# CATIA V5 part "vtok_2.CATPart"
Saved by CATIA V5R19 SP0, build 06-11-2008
Part number: LEGO_v3.1.2
Source: Unknown
Bounding box of the stored display mesh (mm): x -5.907 to 5.893, y 0 to 16.735, z -2.795 to 0
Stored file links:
  C:\Users\jsmid\Desktop\DP_Smidak_Forma LEGO\vtok_2.CATPart
  C:\Users\jsmid\Desktop\Forma_kostka\Babyplast_univ_ram_plus_LEGO_2.CATProduct
  C:\Users\jsmid\Desktop\Forma_kostka\DOC219.CATPart
  Product8.CATProduct
  C:\Users\jsmid\Desktop\Forma_kostka\tvarnik_1.1.CATPart
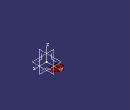
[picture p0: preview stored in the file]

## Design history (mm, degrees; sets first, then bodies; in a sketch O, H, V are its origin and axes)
Parameters
  DraftAngle = 0 deg
  Tesselation1 = 0.01 mm
  Tesselation2 = -1 mm
  `Compute Mode` = 0
  ValExplode = 10 mm
  Stroke = 0 mm
  `Stroke Angle` = 0 deg
AxisSystem1 "Main Pulling Direction.1": origin (0, 0, 0), X (1, 0, 0), Y (0, 1, 0), Z (0, 0, 1)
Set1
  Sketch1 on face of Solid1, origin (0, 0, 0), H (1, 0, 0), V (0, 1, 0)
    line L1 (-1.9073, 13.9547) -> (-1.9073, 12.8178)
    point P2 (-1.9073, 12.8178)
    line L2 (-1.9073, 12.8178) -> (1.8926, 12.8178)
    point P3 (1.8926, 12.8178)
    line L3 (1.8926, 12.8178) -> (1.7576, 12.2309)
    point P4 (1.7576, 12.2309)
    line L4 (1.7576, 12.2309) -> (-1.7723, 12.2309)
    point P5 (-1.7723, 12.2309)
    line L5 (-1.7723, 12.2309) -> (-1.0074, 8.9066)
    point P6 (-1.0074, 8.9066)
    line L6 (-1.0074, 8.9066) -> (0.9927, 8.9066)
    point P7 (0.9927, 8.9066)
    reference projected line E1 (-1.9073, 14.4251) -> (-1.9073, 12.7349) from edge [face of Solid1 | face of Solid1]
    reference projected line E2 (1.8927, 12.7349) -> (1.8926, 14.4251) from edge [face of Solid1 | face of Solid1]
    reference projected line E3 (1.8927, 12.7349) -> (1.4415, 11.0513) from edge [face of Solid1 | face of Solid1]
    reference projected line E4 (-1.4562, 11.0513) -> (-1.9073, 12.7349) from edge [face of Solid1 | face of Solid1]
    reference projected line E5 (-1.0073, 10.1426) -> (-1.0074, 7.9395) from edge [face of Solid1 | face of Solid1]
    reference projected line E6 (0.9927, 10.1426) -> (0.9927, 7.9395) from edge [face of Solid1 | face of Solid1]
    line L7 (-1.4592, 11.195) -> (1.4675, 11.195)
    point P10 (0.9927, 10.1426)
    line L8 (0.9927, 10.1426) -> (0.9927, 6.7335)
    reference projected point E7 (0.9927, 10.1426) from vertex [face of Solid1 | face of Solid1 | face of Solid1]
    length L6 = 2
    length L2 = 3.8
    length L7 = 2.9268
    length L8 = 3.4091
    vertical: L1 V, L8 V
    horizontal: L2 H, L4 H, L6 H, L7 H
    coincidence: L5 P2, P2 E1, P3 E2, P4 E3, P5 E4, P6 E5, P7 E6, E7 P10
  Line1: type PtDir, Direction (1, 0, 0), Start 0, End 4, RefPoint vertex [face of DatumSurface17]
  Line2: type PtDir, Direction (1, 0, 0), Start 0, End 4, RefPoint vertex [face of DatumSurface17 | face of DatumSurface17]
  Line3: type PtDir, Direction (0, 1, 0), Start 0, End 4, RefPoint vertex of Line2
  Line4: type PtDir, Direction (0, 1, 0), Start 0, End 4, RefPoint vertex [face of DatumSurface17 | face of DatumSurface17]
  Line5: type PtDir, Direction (1, 0, 0), Start 0, End 4, RefPoint vertex of Line4
  Line6: type PtDir, Direction (1, 0, 0), Start 0, End 4, RefPoint vertex [face of DatumSurface17]
  Line7: type PtDir, Direction (1, 0, 0), Start 0, End 4, RefPoint vertex [face of DatumSurface1]
  Line8: type PtDir, Direction (0, 1, 0), Start 0, End 4, RefPoint vertex of Line7
  Line9: type PtDir, Direction (0, 1, 0), Start 0, End 4, RefPoint vertex [face of DatumSurface1 | face of DatumSurface1]
  Line10: type PtDir, Direction (1, 0, 0), Start 0, End 4, RefPoint vertex of Line9
  Line11: type PtPt, SecondPoint vertex of Line6, FirstPoint vertex of Line5
  Line12: type PtPt, SecondPoint vertex of Line7, FirstPoint vertex of Line6
  Line13: type PtPt, SecondPoint vertex of Line8, FirstPoint vertex of Line7
  Line14: type PtPt, SecondPoint vertex of Line9, FirstPoint vertex of Line8
  Line15: type PtPt, SecondPoint vertex of Line10, FirstPoint vertex of Line9
  Line16: type PtPt, SecondPoint vertex of Line1, FirstPoint vertex of Line10
  Line17: type PtPt, SecondPoint vertex of Line2, FirstPoint vertex of Line1
  Line18: type PtPt, SecondPoint vertex of Line3, FirstPoint vertex of Line2
  Line19: type PtPt, SecondPoint vertex of Line4, FirstPoint vertex of Line3
  Line20: type PtPt, SecondPoint vertex of Line5, FirstPoint vertex of Line4
  Line21: type PtPt, SecondPoint vertex [face of DatumSurface1], FirstPoint vertex [face of DatumSurface1]
  Line22: type PtDir, Direction (0, 1, 0), Start 0, End 0.5, RefPoint vertex [face of Fill4]
  Line23: type PtDir, Direction (0, 1, 0), Start 0, End 0.5, RefPoint vertex [face of Fill3]
  Line24: type PtPt, SecondPoint vertex of Line23, FirstPoint vertex of Line22
  Sketch2 on DatumSurface7, origin (0, 0, 0), H (1, 0, 0), V (0, 1, 0)
    line L1 (-4.2727, 6.7395) -> (5.6211, 6.7395)
    reference projected line E1 (0.0039, 6.7405) -> (-0.0186, 6.7405) from edge of DatumSurface7
    distance E1 L1 = 0.001
    horizontal: L1 H
Set2 "Core.1"
  DatumSurface1 "TrfSurface.12"
  Fill1: Boundary (edge of DatumSurface1; Line9; Line14; Line8)
  Fill2: Boundary (Line8; Line13; Line7)
  Fill3: Boundary (edge of DatumSurface17; edge of DatumSurface17; edge of DatumSurface1; Line6; Line12; Line7)
  Fill4: Boundary (edge of DatumSurface1; edge of DatumSurface17; edge of DatumSurface1; Line10; Line16; Line1)
  Fill5: Boundary (Line10; Line9; Line15)
  DatumSurface2 "TrfSurface.23"
  DatumSurface3 "TrfSurface.24"
  DatumSurface4 "TrfSurface.25"
  DatumSurface5 "TrfSurface.26"
  DatumSurface6 "TrfSurface.27"
  DatumSurface7 "TrfSurface.28"
  DatumSurface8 "TrfSurface.29"
  Split1: ToCut DatumSurface6, Cutting Sketch2
  Split2: ToCut DatumSurface7, Cutting Sketch2
  Split3: ToCut DatumSurface8, Cutting Sketch2
  Join1: Elements (DatumSurface1; Fill1; Fill2; Fill3; Fill4; Fill5; DatumSurface2; DatumSurface3; DatumSurface4; DatumSurface5; Split1; Split2; Split3)
Set3 "Cavity.1"
  DatumSurface9 "TrfSurface.16"
  DatumSurface10 "TrfSurface.17"
  DatumSurface11 "TrfSurface.18"
  DatumSurface12 "TrfSurface.19"
  DatumSurface13 "TrfSurface.20"
  DatumSurface14 "TrfSurface.21"
  DatumSurface15 "TrfSurface.22"
Set4 "CCV_NoShow.1"
  DatumSurface16 "TrfSurface.11"
  DatumSurface17
Body1 "Body.4" (main body)
  Solid1: solid without history
  Sketch3 on yz-plane, origin (0, 0, 0), H (0, 1, 0), V (0, 0, 1)
    line L1 (-11.3345, 0) -> (12.7349, 0)
    line L2 (12.7349, 0) -> (12.7349, -3.6263)
    point P3 (-11.3345, 0)
    reference projected line E1 (10.1426, 0) -> (7.9395, 0) from edge [face of Solid1 | face of Solid1]
    reference projected line E2 (12.7349, 0) -> (12.7349, -1.6836) from edge [face of Solid1 | face of Solid1]
    line L3 (12.7349, -3.6263) -> (11.4017, -8.34)
    line L4 (11.4017, -8.34) -> (44.039, -8.34)
    line L5 (44.039, -8.34) -> (57.7468, 35.877)
    line L6 (57.7468, 35.877) -> (20.9298, 41.9453)
    line L7 (20.9298, 41.9453) -> (-17.0846, 11.1658)
    line L8 (-17.0846, 11.1658) -> (-11.3345, 0)
    point P9 (-11.3345, 0)
    horizontal: L1 H, L4 H
    vertical: L2 V
    coincidence: L1 E1, L2 E2, P3 L8, P9 P3
  Pocket1: profile Sketch3, direction (-1, 0, 0), length 20, mirrored extent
